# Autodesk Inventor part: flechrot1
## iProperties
Shininess: 64.0
Length Units: 11269
Angle Units: 11279
Time Units: 11290
Mass Units: 11283
Length Display Precision: 3
Angle Display Precision: 2
Compacted: True
Part Number: flechrot1
Document SubType Name: Modeling
Created: 2003-10
Material: Par défaut
Designer: Maison
Density: 0.0
Volumn: 0.0
Area: 0.0
PropertySet Name: Model Information
Control State: 0
Master: False
Checked Out: False
Author: Maison
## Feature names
1. Extrusion1
